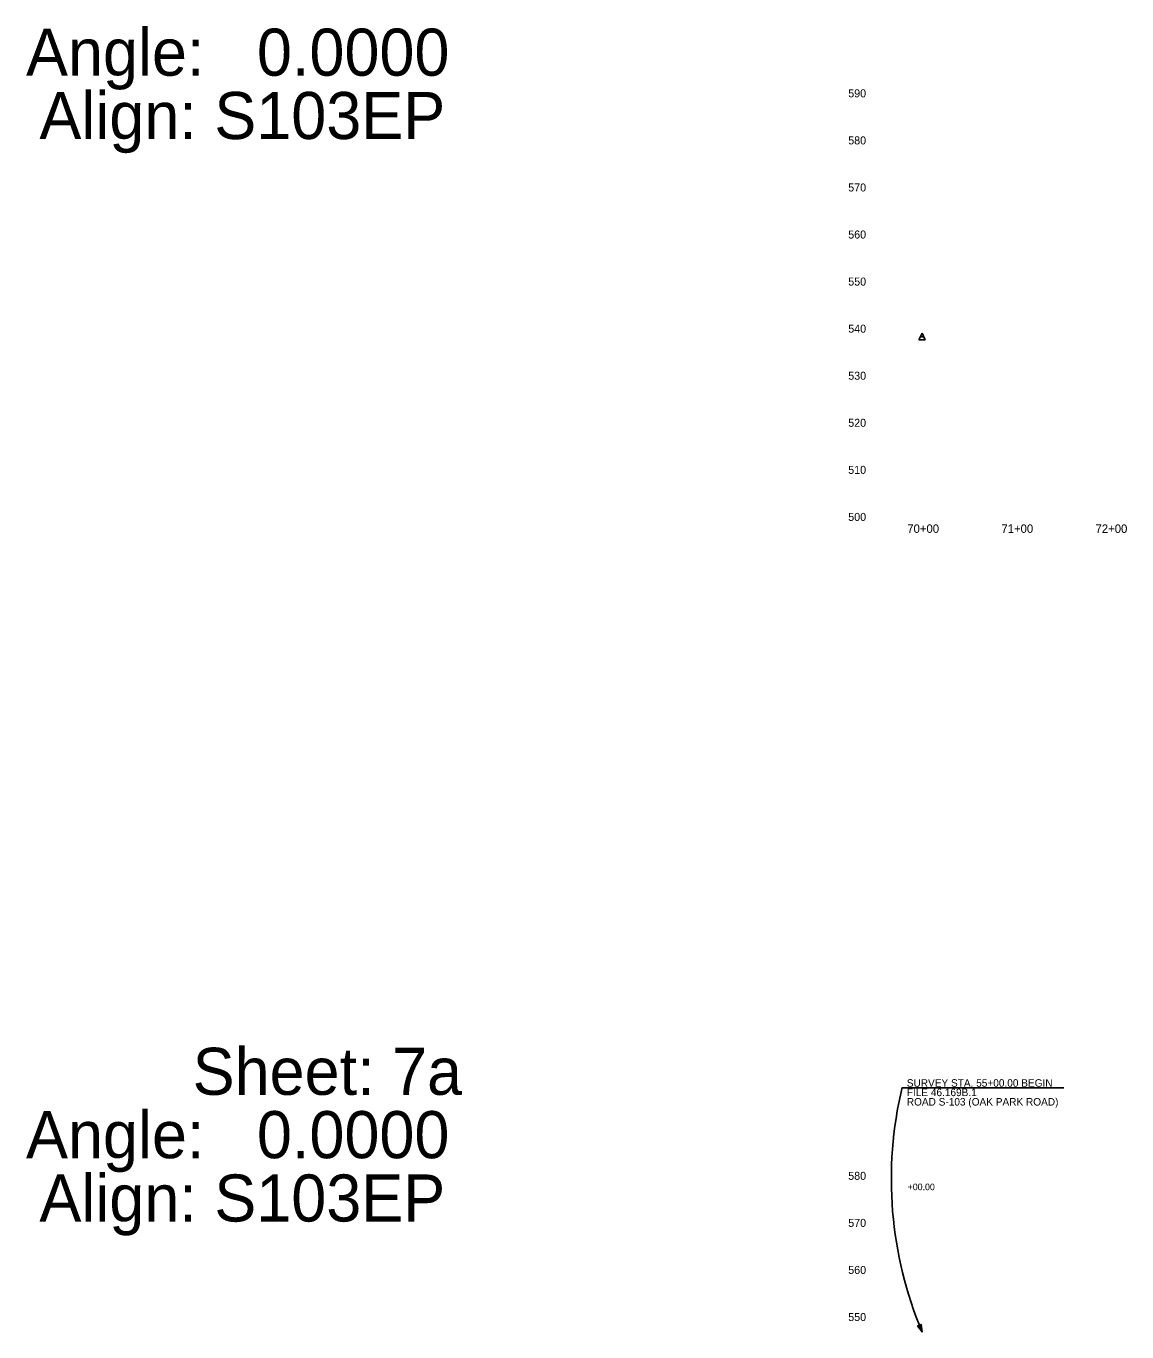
# Model space of a CAD drawing. Extents: x 1959560 to 1962161, y 1107485 to 1113134.
# Drawn here: x 1959632 to 1960801, y 1108937 to 1110324 of the extents above; entities that cross this region are included whole.
import ezdxf

# ---------------------------------------------------------------- set-up
doc = ezdxf.new("R2010")
doc.units = 0
for name, color, linetype in [('Level 21', 7, 'Continuous'), ('Level 41', 7, 'Continuous'), ('Level 42', 7, 'Continuous'), ('Level 60', 7, 'Continuous')]:
    doc.layers.add(name, color=color, linetype=linetype)

msp = doc.modelspace()

# ---------------------------------------------------------------- linework, layer by layer
at = {"layer": 'Level 21'}
msp.add_line((1960734.2, 1109196), (1960562.5, 1109196), dxfattribs=at)
msp.add_lwpolyline([(1960578.8, 1108942.9), (1960583.7, 1108936.6), (1960582.6, 1108944.5)], close=True, dxfattribs=at)
msp.add_arc((1960971.1, 1109098.8), 420, 166.6156, 202.7219, dxfattribs=at)
at = {"layer": 'Level 41'}
for p, q in [((1960583.7, 1109997.6), (1960580.2, 1109990.6)), ((1960583.7, 1109997.6), (1960587.2, 1109990.6)), ((1960580.2, 1109990.6), (1960587.2, 1109990.6))]:
    msp.add_line(p, q, dxfattribs=at)
msp.add_circle((1960583.7, 1109993.6), 0.25, dxfattribs=at)

# ---------------------------------------------------------------- texts
at = {"layer": 'Level 21'}
for s, p in [('SURVEY STA. 55+00.00 BEGIN', (1960567.5, 1109197)), ('FILE 46.169B.1', (1960567.5, 1109187)), ('ROAD S-103 (OAK PARK ROAD)', (1960567.5, 1109177))]:
    msp.add_text(s, height=8, dxfattribs=at).set_placement(p)
at = {"layer": 'Level 41'}
msp.add_text('+00.00', height=7, dxfattribs=at).set_placement((1960568.4, 1109087.1))
at = {"layer": 'Level 42'}
for s, height, p in [('590', 8.5, (1960505.3, 1110248.1)), ('580', 8.5, (1960505.3, 1110198.1)), ('570', 8.5, (1960505.3, 1110148.1)), ('560', 8.5, (1960505.3, 1110098.1)), ('550', 8.5, (1960505.3, 1110048.1)), ('540', 8.5, (1960505.3, 1109998.1)), ('530', 8.5, (1960505.3, 1109948.1)), ('520', 8.5, (1960505.3, 1109898.1)), ('510', 8.5, (1960505.3, 1109848.1)), ('500', 8.5, (1960505.3, 1109798.1)), ('70+00', 9, (1960568, 1109785.4)), ('71+00', 9, (1960668, 1109785.4)), ('72+00', 9, (1960768, 1109785.4)), ('580', 8.5, (1960505.3, 1109098.1)), ('570', 8.5, (1960505.3, 1109048.1)), ('560', 8.5, (1960505.3, 1108998.1)), ('550', 8.5, (1960505.3, 1108948.1))]:
    msp.add_text(s, height=height, dxfattribs=at).set_placement(p)
at = {"layer": 'Level 60'}
for s, p in [('Angle:   0.0000', (1959631.8, 1110271.1)), ('Align: S103EP', (1959646, 1110203.8)), ('Sheet: 7a', (1959808.8, 1109188.4)), ('Angle:   0.0000', (1959631.8, 1109121.1)), ('Align: S103EP', (1959646, 1109053.8))]:
    msp.add_text(s, height=50, dxfattribs=at).set_placement(p)

doc.saveas('drawing.dxf')
